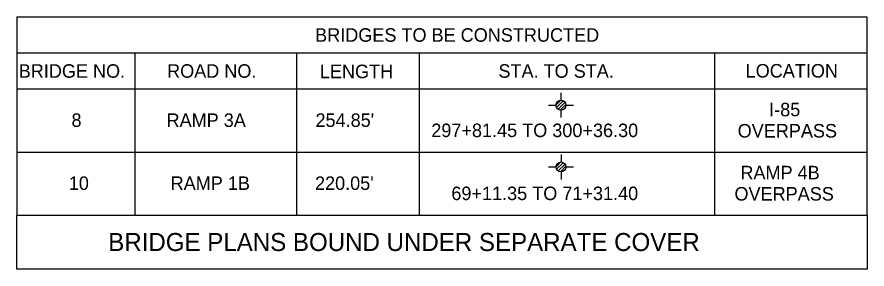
# Model space of a CAD drawing. Extents: x 4932 to 5887, y 4809 to 5473.
# Drawn here: x 4931.8 to 5026.2, y 4868.3 to 4896.3 of the extents above; entities that cross this region are included whole.
import ezdxf

# ---------------------------------------------------------------- set-up
doc = ezdxf.new("R2010")
doc.units = 0
for name, color, linetype in [('Level 3', 7, 'Continuous'), ('RD_EX_SU_Pole', 7, 'Continuous'), ('RD_TX_TitleSht', 7, 'Continuous')]:
    doc.layers.add(name, color=color, linetype=linetype)

# ---------------------------------------------------------------- blocks, each defined once
blk = doc.blocks.new('SUE_TFP')
at = {"layer": 'RD_EX_SU_Pole'}
for p, q in [((0, 5.5), (0, 2.22)), ((-2.21, 0.13), (-0.13, 2.21)), ((-1.96, -1.03), (1.03, 1.96)), ((-1.31, -1.79), (1.79, 1.31)), ((-0.3, -2.2), (2.2, 0.3)), ((2.22, 0), (5.53, 0.01)), ((-5.53, -0.01), (-2.22, 0)), ((0, -2.22), (0, -5.5))]:
    blk.add_line(p, q, dxfattribs=at)
blk.add_circle((0, 0), 2.22, dxfattribs=at)

msp = doc.modelspace()

# ---------------------------------------------------------------- linework, layer by layer
at = {"layer": 'Level 3'}
for p, q in [((4931.783, 4896.298), (5026.161, 4896.298)), ((4931.783, 4896.298), (4931.783, 4874.298)), ((5026.161, 4896.298), (5026.161, 4874.298)), ((4931.783, 4892.298), (5026.161, 4892.298)), ((4962.87, 4874.298), (4962.87, 4892.298)), ((4976.47, 4874.298), (4976.47, 4892.298)), ((5009.27, 4874.298), (5009.27, 4892.298)), ((4931.783, 4888.298), (5026.161, 4888.298)), ((4931.783, 4881.298), (5026.161, 4881.298)), ((4931.783, 4874.298), (5026.161, 4874.298))]:
    msp.add_line(p, q, dxfattribs=at)
msp.add_lwpolyline([(4931.783, 4874.298), (5026.176, 4874.298), (5026.176, 4868.298), (4931.783, 4868.298)], close=True, dxfattribs=at)
at = {"layer": 'RD_TX_TitleSht'}
msp.add_line((4944.87, 4892.298), (4944.87, 4874.298), dxfattribs=at)

# ---------------------------------------------------------------- block references
at = {"layer": 'Level 3', "xscale": 0.24999999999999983, "yscale": 0.24999999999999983}
for p in [(4992.192, 4886.501), (4992.197, 4879.635)]:
    msp.add_blockref('SUE_TFP', p, dxfattribs=at)

# ---------------------------------------------------------------- texts
at = {"layer": 'Level 3'}
for s, height, p in [('BRIDGES TO BE CONSTRUCTED', 1.5, (4964.892, 4893.548)), ('BRIDGE NO.', 1.5, (4931.976, 4889.548)), ('ROAD NO.', 1.5, (4948.454, 4889.548)), ('LENGTH', 1.5, (4965.419, 4889.501)), ('STA. TO STA.', 1.5, (4985.246, 4889.548)), ('LOCATION', 1.5, (5012.698, 4889.573)), ('I-85 ', 1.5, (5015.309, 4885.264)), ('8', 1.5, (4937.837, 4884.085)), ('RAMP 3A', 1.5, (4948.39, 4884.085)), ("254.85'", 1.5, (4964.93, 4884.085)), ('297+81.45 TO 300+36.30', 1.5, (4977.788, 4882.954)), ('OVERPASS', 1.5, (5011.813, 4882.907)), ('RAMP 4B ', 1.5, (5012.119, 4878.262)), ('10', 1.5, (4937.535, 4877.084)), ('RAMP 1B', 1.5, (4948.845, 4877.084)), ('RAMP 1B', 1.5, (4948.845, 4877.084)), ("220.05'", 1.5, (4964.876, 4877.084)), ('69+11.35 TO 71+31.40', 1.5, (4980.02, 4875.952)), ('OVERPASS', 1.5, (5011.458, 4875.905)), ('BRIDGE PLANS BOUND UNDER SEPARATE COVER', 2, (4941.916, 4870.298))]:
    msp.add_text(s, height=height, dxfattribs=at).set_placement(p)

doc.saveas('drawing.dxf')
